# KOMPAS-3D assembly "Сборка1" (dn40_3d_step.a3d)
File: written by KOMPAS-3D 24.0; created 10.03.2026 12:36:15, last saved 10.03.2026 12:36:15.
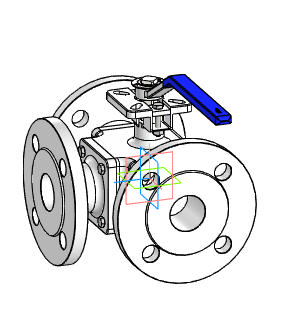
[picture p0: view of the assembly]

Document properties: Автор: R2D2; Полное имя файла: E:\Работа\Зайцев\BV3232P(4pc)-FP-3WL-F-ISO-H Кран шаровой DN.ru Ду15-100 Ру16\DN40\исходные материалы\dn40_3d_step.a3d

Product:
- Component [detail]: Деталь  | qty 1  | Автор: R2D2; source file: Деталь Деталь.m3d
- Component [detail]: Деталь1  | qty 1  | Автор: R2D2; source file: Деталь1 Деталь1.m3d
- Component [detail]: AS 1110 - M6 x 30  | qty 1  | Автор: R2D2; source file: AS 1110 - M6 x 30 AS 1110 - M6 x 30.m3d
- Component [detail]: AS 1110 - M6 x 30  | qty 1  | Комментарий: Болты и винты   шестигранные точные   метрические ISO; Автор: R2D2; additional columns: Сталь, мягкая; source file: AS 1110 - M6 x 30 AS 1110 - M6 x 30.m3d
- Component [detail]: ANSI B18.2.4.2M - M6x1 - 10  | designation ANSI B18.2.4.2M - M6x1  | qty 1  | Автор: R2D2; source file: ANSI B18.2.4.2M - M6x1 ANSI B18.2.4.2M - M6x1 - 10.m3d
- Component [detail]: ANSI B18.2.4.2M - M6x1 - 10  | designation ANSI B18.2.4.2M - M6x1  | qty 1  | Комментарий: Типы метрических   шестигранных гаек   2; Автор: R2D2; additional columns: Сталь, мягкая; source file: ANSI B18.2.4.2M - M6x1 ANSI B18.2.4.2M - M6x1 - 10.m3d
- Component [detail]: AS 1110 - M6 x 12  | qty 1  | Автор: R2D2; source file: AS 1110 - M6 x 12 AS 1110 - M6 x 12.m3d
- Component [detail]: AS 1110 - M6 x 12  | qty 11  | Комментарий: Болты и винты   шестигранные точные   метрические ISO; Автор: R2D2; additional columns: Сталь, мягкая; source file: AS 1110 - M6 x 12 AS 1110 - M6 x 12.m3d
- Part/product: Сборка1

Referenced files in E:\Работа\Зайцев\BV3232P(4pc)-FP-3WL-F-ISO-H Кран шаровой DN.ru Ду15-100 Ру16\DN40\исходные материалы\: Деталь Деталь.m3d, Деталь1 Деталь1.m3d, AS 1110 - M6 x 30 AS 1110 - M6 x 30.m3d, ANSI B18.2.4.2M - M6x1 ANSI B18.2.4.2M - M6x1 - 10.m3d, AS 1110 - M6 x 12 AS 1110 - M6 x 12.m3d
